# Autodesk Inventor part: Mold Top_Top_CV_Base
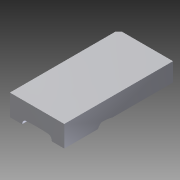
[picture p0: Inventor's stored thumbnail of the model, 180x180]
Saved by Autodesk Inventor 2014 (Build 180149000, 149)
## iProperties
Created: 2009-12
Part Number: Mold Top_Top_CV_Base
Document SubType Name: Modeling
Designer: gaom
Density: 1 g/cm^3
Material: Generic
Appearance: Default
Author: gaom
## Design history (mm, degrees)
node "Mold Top_Top_MP"
feature "Solid4::Mold Top_Top_MP"
tag "TaggingFeature1"
body "Solid1"
